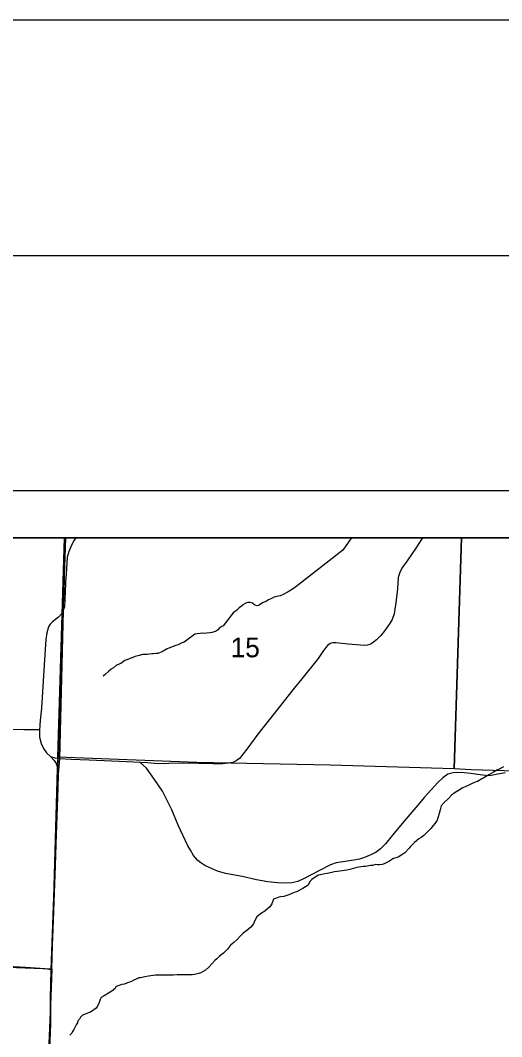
# Model space of a CAD drawing. Extents: x 0 to 34, y 0 to 22.
# Drawn here: x 26.261 to 27.284, y 19.839 to 22 of the extents above; entities that cross this region are included whole.
import ezdxf

# ---------------------------------------------------------------- set-up
doc = ezdxf.new("R2010")
doc.units = 0
for name, color, linetype in [('GM_X_Adjacent_County', 7, 'Continuous'), ('GM_X_County', 7, 'Continuous'), ('GM_X_County_Road', 7, 'Continuous'), ('GM_X_Minor_River', 7, 'Continuous'), ('GM_X_Section', 7, 'Continuous'), ('GM_X_Section_Text', 7, 'Continuous'), ('GM_X_Township', 7, 'Continuous'), ('GM_X_Township_Road', 7, 'Continuous'), ('SH_Border', 7, 'Continuous'), ('SH_Cut_Line', 7, 'Continuous'), ('SH_Data', 7, 'Continuous')]:
    doc.layers.add(name, color=color, linetype=linetype)

msp = doc.modelspace()

# ---------------------------------------------------------------- linework, layer by layer
at = {"layer": 'GM_X_Adjacent_County'}
msp.add_lwpolyline([(30.8167, 17.8174), (30.8167, 20.9), (24.0167, 20.9), (24.0167, 18.0693)], dxfattribs=at)
at = {"layer": 'GM_X_County'}
msp.add_lwpolyline([(30.8167, 17.8174), (30.8167, 20.9), (24.0167, 20.9), (24.0167, 18.0693)], dxfattribs=at)
at = {"layer": 'GM_X_County_Road'}
for points in [[(26.3785, 20.9), (26.3749, 20.8946), (26.3704, 20.8858), (26.3636, 20.8707), (26.3602, 20.8588), (26.3602, 20.8572)], [(26.3602, 20.8572), (26.3596, 20.8465), (26.3578, 20.8234), (26.3567, 20.8048), (26.3558, 20.7842), (26.3546, 20.7528), (26.3526, 20.7475)], [(26.3526, 20.7475), (26.3517, 20.745), (26.3484, 20.7381), (26.3415, 20.7313), (26.3289, 20.7214), (26.3238, 20.7159), (26.3202, 20.7101), (26.3167, 20.6979), (26.315, 20.6832), (26.3116, 20.6294), (26.3059, 20.5377), (26.3033, 20.5185), (26.302, 20.5028), (26.3018, 20.5002), (26.3016, 20.4911), (26.3017, 20.4759), (26.3048, 20.4623), (26.3099, 20.4517), (26.3162, 20.4423), (26.3253, 20.4343), (26.3323, 20.4264), (26.3366, 20.4199), (26.3392, 20.4137), (26.3401, 20.406), (26.3405, 20.399)], [(26.3405, 20.399), (26.3407, 20.3932), (26.3403, 20.3674), (26.336, 20.2481), (26.3348, 20.2025), (26.3299, 20.0679), (26.326, 19.9813), (26.325, 19.9211), (26.3245, 19.8669), (26.3238, 19.8473), (26.3228, 19.8154), (26.3228, 19.8045), (26.3235, 19.7961), (26.3245, 19.7924)]]:
    msp.add_lwpolyline(points, dxfattribs=at)
at = {"layer": 'GM_X_Minor_River'}
for points in [[(26.9644, 20.9), (26.9591, 20.8921), (26.9564, 20.8876), (26.9527, 20.8823), (26.9462, 20.8735), (26.8461, 20.7952), (26.8392, 20.7906), (26.8298, 20.7849), (26.8192, 20.7792), (26.8128, 20.7761), (26.8063, 20.775), (26.8003, 20.7735), (26.7946, 20.7708), (26.7885, 20.7681), (26.784, 20.7647), (26.7753, 20.7613), (26.7685, 20.7567), (26.7639, 20.7548), (26.7594, 20.7563), (26.7541, 20.7608), (26.7495, 20.7624), (26.7442, 20.762), (26.7397, 20.7604), (26.7351, 20.7578), (26.7306, 20.7547), (26.7257, 20.7509), (26.7208, 20.746), (26.7132, 20.7399), (26.706, 20.7308), (26.7019, 20.7255), (26.6917, 20.7125), (26.6849, 20.7087), (26.68, 20.7034), (26.6754, 20.7007), (26.6679, 20.6985), (26.6633, 20.6977), (26.6565, 20.6969), (26.6527, 20.6965), (26.6482, 20.6969), (26.6432, 20.6961), (26.636, 20.6957), (26.6315, 20.695), (26.6251, 20.6896), (26.6202, 20.6866), (26.6088, 20.6778), (26.6024, 20.6756), (26.5963, 20.6725), (26.591, 20.6706), (26.5853, 20.6687), (26.5766, 20.6653), (26.5725, 20.6634), (26.5645, 20.6584), (26.56, 20.6569), (26.5532, 20.6538), (26.549, 20.6534), (26.5437, 20.6531)], [(26.5437, 20.6531), (26.5399, 20.6527), (26.5304, 20.6519), (26.5267, 20.6515), (26.521, 20.6515), (26.513, 20.6496), (26.5047, 20.6473), (26.4926, 20.6427), (26.4831, 20.6385), (26.474, 20.6328), (26.4653, 20.6286), (26.4585, 20.6233), (26.4536, 20.6206), (26.4491, 20.6161), (26.4411, 20.6088), (26.437, 20.6058)], [(27.2875, 20.4129), (27.2788, 20.4076), (27.2747, 20.4061), (27.2667, 20.4015), (27.2569, 20.3958), (27.2459, 20.3893), (27.2414, 20.387), (27.2323, 20.3817), (27.2277, 20.3802), (27.2198, 20.3764), (27.2156, 20.3748), (27.2088, 20.3714), (27.2001, 20.3672), (27.1918, 20.3623), (27.185, 20.3581), (27.177, 20.3528), (27.171, 20.3455), (27.1619, 20.3372), (27.1555, 20.33), (27.1529, 20.3216), (27.151, 20.3133), (27.1491, 20.3064), (27.1469, 20.2992), (27.1424, 20.2931), (27.1382, 20.2878), (27.1333, 20.2814), (27.1242, 20.2722), (27.1182, 20.2669), (27.1125, 20.2627), (27.108, 20.2597), (27.1031, 20.2555), (27.0989, 20.2517), (27.0948, 20.2483), (27.0902, 20.2433), (27.0872, 20.2395), (27.0781, 20.23), (27.0736, 20.2274), (27.0638, 20.2209), (27.0592, 20.2194), (27.0543, 20.2179), (27.0441, 20.2114), (27.0343, 20.2068), (27.0297, 20.2053), (27.0244, 20.2045), (27.0199, 20.2045), (27.0161, 20.2049), (27.0093, 20.2033), (27.0051, 20.203), (26.9979, 20.2014), (26.9941, 20.201), (26.9899, 20.2007), (26.985, 20.2003), (26.9759, 20.1987), (26.971, 20.1976), (26.9608, 20.1941), (26.9547, 20.193), (26.9449, 20.1918), (26.9396, 20.1907), (26.9282, 20.1895), (26.9229, 20.1884), (26.9127, 20.1857), (26.9078, 20.1853), (26.8987, 20.1834), (26.8945, 20.1823), (26.8873, 20.1784)], [(26.8873, 20.1784), (26.8805, 20.1731), (26.8764, 20.1686), (26.8726, 20.161), (26.8609, 20.1541), (26.848, 20.1473), (26.8431, 20.1457), (26.8366, 20.1427), (26.8314, 20.1408), (26.8272, 20.1389), (26.8211, 20.1373), (26.8147, 20.1362), (26.8105, 20.1354), (26.803, 20.1328), (26.7988, 20.1312), (26.795, 20.1214), (26.7909, 20.1153), (26.7807, 20.1058), (26.7712, 20.1005), (26.7633, 20.0936), (26.7595, 20.086), (26.7565, 20.0788), (26.7509, 20.0716), (26.7425, 20.0647), (26.7346, 20.059), (26.7282, 20.0526), (26.7218, 20.0454), (26.7142, 20.0393), (26.7078, 20.0336), (26.701, 20.0252), (26.6927, 20.0165), (26.684, 20.01), (26.6783, 20.0047), (26.6745, 20.0009), (26.6681, 19.994), (26.6617, 19.9868), (26.6541, 19.9807), (26.6443, 19.9746), (26.6401, 19.9731), (26.6307, 19.9712), (26.6257, 19.9708), (26.6155, 19.9704), (26.611, 19.9708), (26.6, 19.9708), (26.5939, 19.9704), (26.5863, 19.9696), (26.5787, 19.9696), (26.575, 19.97), (26.5678, 19.9696), (26.5628, 19.9699), (26.553, 19.9695), (26.5477, 19.9695), (26.5378, 19.9684), (26.5333, 19.9676), (26.5253, 19.9664), (26.5162, 19.9641), (26.5125, 19.9638), (26.5083, 19.9619), (26.5007, 19.9584), (26.4954, 19.9554), (26.4909, 19.9539), (26.4814, 19.9504), (26.4761, 19.9496), (26.4685, 19.947), (26.4644, 19.9458), (26.4614, 19.9409), (26.4553, 19.936), (26.4481, 19.9314), (26.4387, 19.9257), (26.4326, 19.9226), (26.4307, 19.9177), (26.4285, 19.9116), (26.4255, 19.9055), (26.4217, 19.8995), (26.4096, 19.8911), (26.4054, 19.8896), (26.3986, 19.8869), (26.3926, 19.8846), (26.3888, 19.8808), (26.3862, 19.8763), (26.3831, 19.8725), (26.382, 19.8687), (26.3794, 19.8645), (26.3767, 19.8588), (26.3741, 19.8542), (26.3715, 19.8501), (26.3703, 19.8463), (26.3662, 19.8421)]]:
    msp.add_lwpolyline(points, dxfattribs=at)
at = {"layer": 'GM_X_Section'}
for p, q in [((26.3546, 20.9), (25.3948, 20.9)), ((27.1988, 20.9), (26.3546, 20.9)), ((27.691, 20.9), (27.1988, 20.9))]:
    msp.add_line(p, q, dxfattribs=at)
for points in [[(25.3948, 20.9), (25.3473, 20.02), (26.3274, 19.9835), (26.3407, 20.4337), (26.3546, 20.9)], [(26.3546, 20.9), (26.3407, 20.4337), (26.6361, 20.4225), (26.9192, 20.4168), (27.1828, 20.409), (27.1988, 20.9)], [(27.1988, 20.9), (27.1828, 20.409), (27.2191, 20.4074), (27.5221, 20.3981), (27.8158, 20.3902), (28.0896, 20.3825), (28.1829, 20.3798), (28.1991, 20.8853), (27.691, 20.9)]]:
    msp.add_lwpolyline(points, dxfattribs=at)
msp.add_lwpolyline([(25.3473, 20.02), (26.3274, 19.9835), (26.3256, 19.9238), (26.3052, 19.4442), (26.2872, 18.9674), (25.2935, 19.0114)], close=True, dxfattribs=at)
at = {"layer": 'GM_X_Township'}
for points in [[(26.3564, 20.9), (24.0167, 20.9), (24.0167, 18.0693)], [(26.2579, 18.0444), (26.2775, 18.5614), (26.3204, 19.5672), (26.3254, 19.7889), (26.3235, 19.7961), (26.3228, 19.8045), (26.3228, 19.8154), (26.3238, 19.8473), (26.3245, 19.8669), (26.325, 19.9211), (26.326, 19.9813), (26.3403, 20.3674), (26.341, 20.3982), (26.344, 20.4298), (26.3517, 20.745), (26.352, 20.7571), (26.3529, 20.7844), (26.3538, 20.8148), (26.354, 20.8204), (26.3551, 20.8572), (26.3564, 20.9)], [(26.3564, 20.9), (26.3551, 20.8572), (26.354, 20.8204), (26.3538, 20.8148), (26.3529, 20.7844), (26.352, 20.7571), (26.3517, 20.745), (26.344, 20.4298), (26.341, 20.3982), (26.3403, 20.3674), (26.326, 19.9813), (26.325, 19.9211), (26.3245, 19.8669), (26.3238, 19.8473), (26.3228, 19.8154), (26.3228, 19.8045), (26.3235, 19.7961), (26.3254, 19.7889), (26.3204, 19.5672), (26.2775, 18.5614), (26.2579, 18.0444)], [(30.8167, 17.8174), (30.8167, 20.9), (26.3564, 20.9)]]:
    msp.add_lwpolyline(points, dxfattribs=at)
at = {"layer": 'GM_X_Township_Road'}
for points in [[(27.1157, 20.9), (27.1154, 20.8996), (27.1012, 20.878), (27.0831, 20.8511), (27.0716, 20.8353), (27.0671, 20.8258), (27.0642, 20.8153), (27.0624, 20.7921), (27.0599, 20.7671), (27.0552, 20.7383), (27.0511, 20.7258), (27.0472, 20.7188), (27.0404, 20.7095), (27.0334, 20.7001), (27.026, 20.6913), (27.0178, 20.6828), (27.0112, 20.6777), (27.0065, 20.6746), (27.0034, 20.6726), (26.9985, 20.6711), (26.9921, 20.6709), (26.9837, 20.6711), (26.9578, 20.6736), (26.9317, 20.6767), (26.9252, 20.6763), (26.9196, 20.675), (26.9139, 20.6705), (26.9104, 20.6664), (26.904, 20.6578), (26.8935, 20.6434), (26.8594, 20.6001), (26.8426, 20.5799), (26.8138, 20.5432), (26.7657, 20.4821), (26.7423, 20.4501), (26.7265, 20.4308), (26.7193, 20.4252), (26.7123, 20.422), (26.7035, 20.4203), (26.691, 20.4191), (26.6704, 20.4191), (26.6072, 20.4205), (26.5766, 20.4195), (26.5538, 20.4193), (26.5308, 20.4216), (26.5153, 20.4221), (26.4863, 20.4234), (26.4068, 20.4267), (26.3685, 20.4283), (26.344, 20.4298), (26.3346, 20.4314), (26.3253, 20.4343)], [(26.3016, 20.4911), (26.2681, 20.4917), (26.2277, 20.4922)], [(27.2917, 20.4), (27.2724, 20.3963), (27.2578, 20.3938), (27.2492, 20.394), (27.2326, 20.3967), (27.2186, 20.3988), (27.2045, 20.4), (27.1907, 20.4004), (27.1811, 20.4), (27.1698, 20.3971), (27.1585, 20.3897), (27.1479, 20.3792), (27.1193, 20.3472), (27.1057, 20.3314), (27.076, 20.2965), (27.0518, 20.2676), (27.0372, 20.2493), (27.0263, 20.2383), (27.0171, 20.2315), (27.007, 20.2264), (26.9922, 20.2202), (26.9818, 20.2167), (26.9693, 20.214), (26.9462, 20.211), (26.9321, 20.2085), (26.9202, 20.2042), (26.897, 20.1923), (26.882, 20.1845), (26.8641, 20.1756), (26.8504, 20.1691), (26.8377, 20.1662), (26.8247, 20.1652), (26.8071, 20.1658), (26.7866, 20.1683), (26.7628, 20.1728), (26.7324, 20.1793), (26.6967, 20.1861), (26.6798, 20.1908), (26.6605, 20.1993), (26.6527, 20.203), (26.6441, 20.2089), (26.6382, 20.2135), (26.6288, 20.2242), (26.6222, 20.2356), (26.6168, 20.245), (26.5961, 20.289), (26.5827, 20.3214), (26.568, 20.3509), (26.563, 20.361), (26.5462, 20.3858), (26.5292, 20.4102), (26.5153, 20.4221)], [(26.326, 19.9813), (26.3135, 19.983), (26.2717, 19.986), (26.2343, 19.9879)]]:
    msp.add_lwpolyline(points, dxfattribs=at)
at = {"layer": 'SH_Border'}
msp.add_lwpolyline([(2, 21.5), (33.5, 21.5), (33.5, 0.5), (2, 0.5)], close=True, dxfattribs=at)
at = {"layer": 'SH_Cut_Line'}
msp.add_lwpolyline([(0, 0), (34, 0), (34, 22), (0, 22)], close=True, dxfattribs=at)
at = {"layer": 'SH_Data'}
for points in [[(23.9167, 21), (30.9167, 21), (30.9167, 14), (23.9167, 14)], [(24.0167, 20.9), (30.8167, 20.9), (30.8167, 14.1), (24.0167, 14.1)]]:
    msp.add_lwpolyline(points, close=True, dxfattribs=at)

# ---------------------------------------------------------------- texts
at = {"layer": 'GM_X_Section_Text'}
msp.add_text('15', height=0.04186, rotation=0, dxfattribs=at).set_placement((26.7076, 20.6457))

doc.saveas('drawing.dxf')
